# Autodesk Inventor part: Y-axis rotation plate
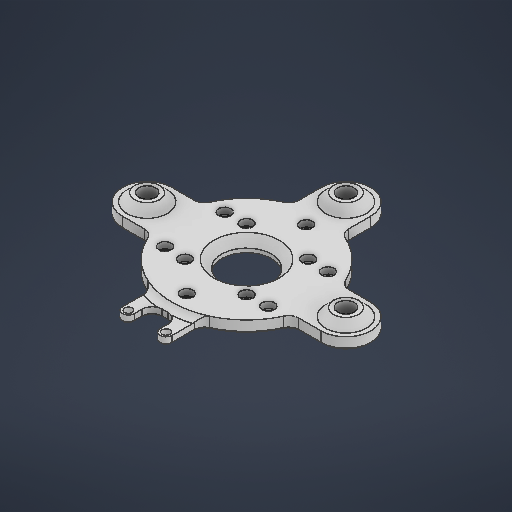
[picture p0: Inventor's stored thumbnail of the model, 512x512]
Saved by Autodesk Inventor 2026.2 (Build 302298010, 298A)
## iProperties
Created: 2026-04
Part Number: Y-axis rotation plate
Material: 일반
Document SubType Name: Modeling
Designer: work
Density: 1 g/cm^3
Appearance: 기본값
Author: work
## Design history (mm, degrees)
sketch "스케치1" dims "d28" = 6
  geometry: L1 (-15.5, 15.5)-(15.5, 15.5); L2 (15.5, 15.5)-(15.5, -15.5); L3 (15.5, -15.5)-(-15.5, -15.5); L4 (-15.5, -15.5)-(-15.5, 15.5); L5 (-15.5, 15.5)-(15.5, -15.5); L6 (15.5, 15.5)-(-15.5, -15.5); L7 (0, 0)-(50, 0); L8 (0, 0)-(0, -50); L9 (0, 0)-(-50, 0); L10 (35.355, 12.5)-(50, 12.5); L11 (35.355, -12.5)-(50, -12.5); L12 (12.5, 35.355)-(12.5, 50); L13 (-12.5, 35.355)-(-12.5, 50); L14 (-35.355, 12.5)-(-50, 12.5); L15 (-35.355, -12.5)-(-50, -12.5); L16 (-12.5, -35.355)-(-12.5, -50); L17 (12.5, -35.355)-(12.5, -50); L18 (-9.5, 50)-(9.5, 50); L19 (6.5, 50)-(6.5, 41); L20 (6.5, 41)-(-6.5, 41); L21 (-6.5, 41)-(-6.5, 50); L22 (12.5, 50)-(12.5, 35.355); L23 (-12.5, 50)-(-12.5, 35.355); C1 r 12.5 at (0, 0); C2 r 4.25 at (50, 0); C3 r 4.25 at (0, -50); C4 r 4.25 at (-50, 0); C5 r 2 at (15.5, 15.5); C6 r 2 at (-15.5, 15.5); C7 r 2 at (-15.5, -15.5); C8 r 2 at (15.5, -15.5); C9 r 2 at (0, -30); C10 r 2 at (25.981, -15); C11 r 2 at (25.981, 15); C12 r 2 at (0, 30); C13 r 2 at (-25.981, 15); C14 r 2 at (-25.981, -15); C15 r 2 at (9.5, 50); C16 r 2 at (-9.5, 50); A1 r 37.5 centre (0, 0) between (35.355, 12.5) and (35.355, -12.5); A2 r 12.5 centre (50, 0) between (50, -12.5) and (50, 12.5); A3 r 12.5 centre (0, 50) between (12.5, 50) and (-12.5, 50); A4 r 12.5 centre (-50, 0) between (-50, 12.5) and (-50, -12.5); A5 r 12.5 centre (0, -50) between (-12.5, -50) and (12.5, -50); A6 r 3 centre (9.5, 50) between (12.5, 50) and (6.5, 50); 13 further points
  constraints: 46 end point, 22 centre point, 13 coincident, 12 point on circle, 5 horizontal, 5 perpendicular, 4 equal length, 4 midpoint, 3 point on line, 3 tangent, 1 concentric, 1 vertical, 53 other
  dimensions: "d0" = 31 distance of L2.end L3.end; "d1" = 31 distance of L1.end L2.end; "d2" = 25 diameter of C1; "d3" = 50 distance of L7.start L7.end; "d4" = 50 distance of L7.start L8.end; "d5" = 8.5 diameter of C2; "d6" = 8.5 diameter of C3; "d7" = 50 distance of L7.start L9.end; "d8" = 8.5 diameter of C4; "d9" = 4 diameter of C5; "d10" = 4 diameter of C6; "d11" = 4 diameter of C7; "d12" = 4 diameter of C8; "d13" = 4 diameter of C9; "d14" = 30 distance of L7.start C9.centre; "d17" = 360 deg dimension on L7.start C9.centre (derived); "d19" = 75 diameter of A1; "d20" = 25 distance from line of point (42.678, 12.5) L11; "d23" = 360 deg dimension on L7.start A2.centre (derived); "d25" = 19 distance of L18.start L18.end; "d26" = 4 diameter of C15; "d27" = 4 diameter of C16; "d29" = 9 distance from line of L18.end L20
  node "스케치 - 원형 패턴1" dims "d17" = 360 deg (derived)
  node "스케치 - 원형 패턴2" dims "d23" = 360 deg (derived)
extrude "돌출1" new body sketch "스케치1" distance "d30" = 6; taper "d31" = 0 deg
extrude "돌출2" join sketch "스케치1" distance "d32" = 4; taper "d33" = 0 deg
extrude "돌출3" join sketch "스케치1" distance "d34" = 2; taper "d35" = 0 deg
sketch "스케치2"
  geometry: L1 (35.355, -12.5)-(50, -12.5) reference; L2 (50, 12.5)-(35.355, 12.5) reference; L3 (12.5, 35.355)-(12.5, 50) reference; L4 (-12.5, 50)-(-12.5, 35.355) reference; L5 (-35.355, 12.5)-(-50, 12.5) reference; L6 (-50, -12.5)-(-35.355, -12.5) reference; C1 r 4.25 at (-50, 0) reference; C2 r 4.25 at (50, 0) reference; C3 r 4.25 at (0, 50) reference; C4 r 2 at (25.981, 15) reference; C5 r 2 at (25.981, -15) reference; C6 r 2 at (0, -30) reference; C7 r 2 at (-25.981, -15) reference; C8 r 2 at (-25.981, 15) reference; C9 r 2 at (0, 30) reference; C10 r 2 at (-15.5, 15.5) reference; C11 r 2 at (15.5, 15.5) reference; C12 r 2 at (15.5, -15.5) reference; C13 r 2 at (-15.5, -15.5) reference; C14 r 12.5 at (0, 0) reference; C15 r 6.25 at (50, 0); A1 r 12.5 centre (50, 0) between (50, -12.5) and (50, 12.5) reference; A2 r 37.5 centre (0, 0) between (35.355, 12.5) and (12.5, 35.355) reference; A3 r 12.5 centre (0, 50) between (12.5, 50) and (-12.5, 50) reference; A4 r 37.5 centre (0, 0) between (-12.5, 35.355) and (-35.355, 12.5) reference; A5 r 12.5 centre (-50, 0) between (-50, 12.5) and (-50, -12.5) reference; A6 r 37.5 centre (0, 0) between (-35.355, -12.5) and (35.355, -12.5) reference; 1 further point
  constraints: 1 centre point, 1 coincident
  dimensions: "d36" = 2 radial gap between concentric circles of C15 C2
extrude "돌출4" join sketch "스케치2" distance "d37" = 4; taper "d38" = 0 deg
chamfer "모따기1" distance "d39" = 4; stored, may be unused: second distance "d40" = 2, angle "d41" = 45 deg
sketch "스케치4"
  geometry: L1 (35.355, -12.5)-(50, -12.5) reference; L2 (50, 12.5)-(35.355, 12.5) reference; L3 (12.5, 35.355)-(12.5, 50) reference; L4 (-12.5, 50)-(-12.5, 35.355) reference; L5 (-35.355, 12.5)-(-50, 12.5) reference; L6 (-50, -12.5)-(-35.355, -12.5) reference; C1 r 10.25 at (0, 50) reference; C2 r 2 at (-15.5, -15.5) reference; C3 r 2 at (15.5, -15.5) reference; C4 r 2 at (15.5, 15.5) reference; C5 r 2 at (-15.5, 15.5) reference; C6 r 2 at (0, 30) reference; C7 r 2 at (-25.981, 15) reference; C8 r 2 at (-25.981, -15) reference; C9 r 2 at (0, -30) reference; C10 r 2 at (25.981, -15) reference; C11 r 2 at (25.981, 15) reference; C12 r 10.25 at (50, 0) reference; C13 r 10.25 at (-50, 0) reference; A1 r 12.5 centre (50, 0) between (50, -12.5) and (50, 12.5) reference; A2 r 37.5 centre (0, 0) between (35.355, 12.5) and (12.5, 35.355) reference; A3 r 12.5 centre (0, 50) between (12.5, 50) and (-12.5, 50) reference; A4 r 37.5 centre (0, 0) between (-12.5, 35.355) and (-35.355, 12.5) reference; A5 r 12.5 centre (-50, 0) between (-50, 12.5) and (-50, -12.5) reference; A6 r 37.5 centre (0, 0) between (-35.355, -12.5) and (35.355, -12.5) reference; 11 further points
  constraints: 10 coincident
hole "구멍2" sketch "스케치4" at (0, 30), (15.5, 15.5), (25.981, 15), (15.5, -15.5), (25.981, -15), (0, -30), (-15.5, -15.5), (-15.5, 15.5), (-25.981, 15), (-25.981, -15) diameter "d52" = 4; stored, may be unused: countersink angle "d56" = 90 deg, drill point angle "d58" = 118 deg; dims "d53" = 6, "d54" = 6.2, "d55" = 3.2, "d57" = 8
fillet "모깎기1" dims "d59" = 5
chamfer "모따기2" distance "d60" = 1; stored, may be unused: second distance "d61" = 2, angle "d62" = 45 deg
node "솔리드1"
pattern_circular "원형 패턴1" dims angle "d43" = 360 deg
node "투영된 루프1"
node "투영된 루프2"
feature "A9D066F2-1C7D-4E18-AEED-F7BC21143FA4" dims "d52" = 4, "d53" = 6, "d54" = 6.2, "d55" = 3.2, "d56" = 90 deg, "d57" = 8, "d58" = 118 deg
